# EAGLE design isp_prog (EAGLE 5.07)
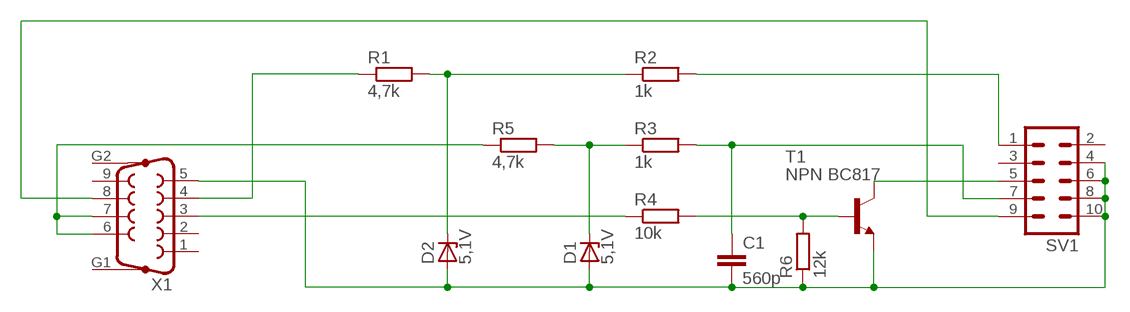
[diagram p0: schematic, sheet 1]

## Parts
C1  560p  C-EUC0805  [C0805]
D1  5,1V  ZENER-DIODESOD80C  [SOD80C]
D2  5,1V  ZENER-DIODESOD80C  [SOD80C]
R1  4,7k  R-EU_R0805  [R0805]
R2  1k  R-EU_R0805  [R0805]
R3  1k  R-EU_R0805  [R0805]
R4  10k  R-EU_R0805  [R0805]
R5  4,7k  R-EU_R0805  [R0805]
R6  12k  R-EU_R0805  [R0805]
SV1  ML10  [ML10]
T1  NPN BC817  BC817-16-NPN-SOT23-BEC  [SOT23-BEC]
X1  F09HP  [F09HP]

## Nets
GND: C1.2 D1.A D2.A R6.1 SV1.4 SV1.6 SV1.8 SV1.10 T1.E X1.5
N$2: R4.2 R6.2 T1.B
N$4: SV1.5 T1.C
N$5: D2.C R1.2 R2.1
N$6: D1.C R3.1 R5.2
N$7: C1.1 R3.2 SV1.7
N$8: R4.1 X1.3
N$9: R5.1 X1.6 X1.7
N$10: R2.2 SV1.1
N$11: SV1.9 X1.8
N$12: R1.1 X1.4
Unconnected: SV1.2 SV1.3 X1.1 X1.2 X1.9 X1.G1 X1.G2

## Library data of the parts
C1 = rcl:C-EU: CAPACITOR, European symbol
D1 D2 = diode:ZENER-DIODE: Z-Diode
R1-R6 = resistor:R-EU_: RESISTOR, European symbol
SV1 = con-harting-ml:ML10: HARTING
T1 = transistor:*-NPN-: NPN Transistror BF959 corrected 2008.03.06
X1 = con-subd:F09HP: SUB-D

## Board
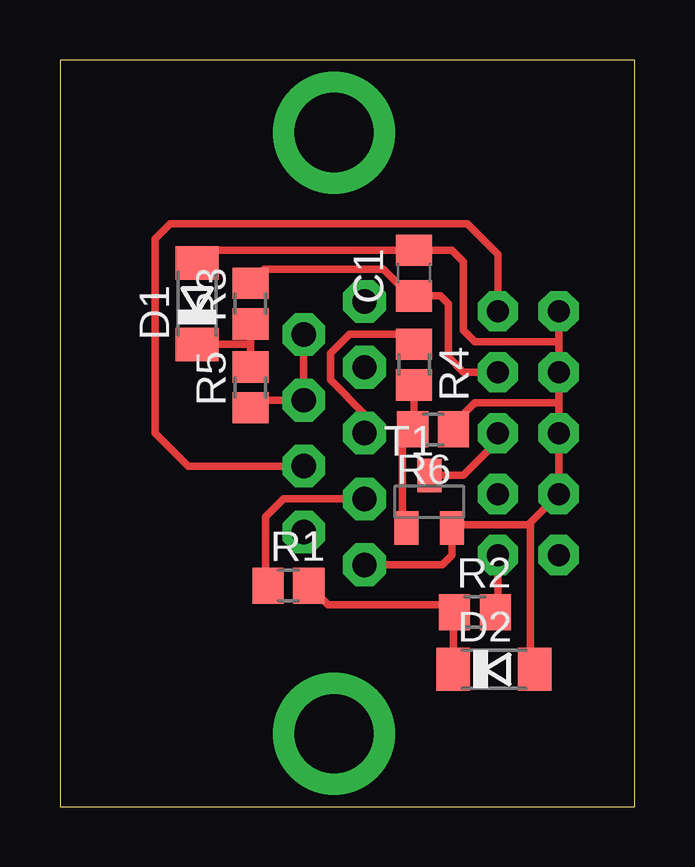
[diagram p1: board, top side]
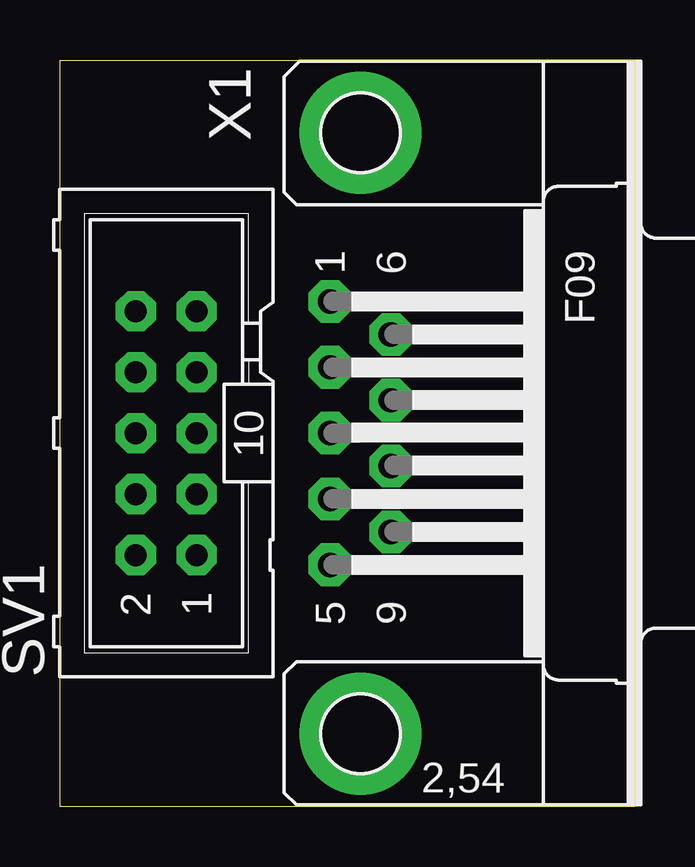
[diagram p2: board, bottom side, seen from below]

Size 23.96 x 31.11 mm. Coordinates in mm from the lower left corner, seen from the top.
Outline: 0,0 23.96,0 23.96,31.11 0,31.11 0,0
Copper layers (1*16): Top 0.035mm / dielectric 1.5mm / Bottom 0.035mm
Design rules "default *": minimum track width 10mil, minimum drill 24mil, track to track 8mil, track to pad 8mil, pad to pad 8mil, via to via 8mil, smd to smd 8mil, copper to edge 40mil, drill to drill 8mil, minimum pad ring 15mil, minimum via ring 8mil, stop-mask expansion 4mil, vias tented up to drill 0mil, thermal gap 10mil

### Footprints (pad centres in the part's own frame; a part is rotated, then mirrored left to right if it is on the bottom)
C0805 = smd 1.3 x 1.5: 1 -0.95,0; 2 0.95,0
SOD80C = smd 1.4 x 1.8: A 1.7,0; C -1.7,0
R0805 = smd 1.3 x 1.5: 1 -0.85,0; 2 0.85,0
ML10 = drill 0.914 octagon: 1 -5.08,-1.27; 2 -5.08,1.27; 3 -2.54,-1.27; 4 -2.54,1.27; 5 0,-1.27; 6 0,1.27; 7 2.54,-1.27; 8 2.54,1.27; 9 5.08,-1.27; 10 5.08,1.27
SOT23-BEC = smd 1 x 1.4: B -0.95,-1.1; C 0,1.1; E 0.95,-1.1
F09HP = drill 1.016 octagon: 1 -5.486,-1.27; 2 -2.743,-1.27; 3 0,-1.27; 4 2.743,-1.27; 5 5.486,-1.27; 6 -4.115,1.27; 7 -1.372,1.27; 8 1.372,1.27; 9 4.115,1.27 | drill 3.302 pad 5.08 round: G1 -12.522,0; G2 12.522,0

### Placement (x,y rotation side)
C1  14.76,22.23 90 top
D1  5.72,20.95 90 top
D2  18.1,5.72 0 top
R1  9.52,9.21 0 top
R2  17.3,8.1 0 top
R3  7.94,20.96 90 top
R4  14.76,18.41 270 top
R5  7.94,17.46 90 top
R6  15.56,15.72 180 top
SV1  19.53,15.56 90 bottom
T1  15.4,12.7 0 top
X1  11.43,15.56 270 bottom

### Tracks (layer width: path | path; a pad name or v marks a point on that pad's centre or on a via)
GND
  Top 0.305: 20.8,16.83 SV1.6 SV1.4 19.61,11.83 | 20.8,16.83 SV1.8 20.8,19.37 | 20.8,19.37 SV1.10 | X1.5 15.95,10.07 16.35,10.48 T1.E 16.52,11.6 16.67,11.75 19.53,11.75 19.61,11.83 | R6.1 16.41,15.93 17.3,16.83 20.8,16.83 | 20.8,19.37 17.3,19.37 16.83,19.84 16.83,22.7 16.35,23.18 C1.2 6.24,23.18 D1.A | 19.61,11.83 19.61,5.91 D2.A
N$2
  Top 0.305: R6.2 14.92,15.72 14.61,15.4 | T1.B 14.29,11.76 14.29,15.3 R6.2 | R4.2 14.76,15.77 R6.2
N$4
  Top 0.305: T1.C 16.82,13.8 17.94,14.92 17.94,15.24 SV1.5
N$5
  Top 0.305: D2.C 16.4,8.04 | 16.4,8.04 R2.1 | 16.4,8.04 16.4,8.05 16.03,8.41 11.17,8.41 R1.2
N$6
  Top 0.305: 7.94,19.21 R3.1 | 7.94,19.21 R5.2 | R3.1 | D1.C 7.89,19.25 7.94,19.21
N$7
  Top 0.305: SV1.7 16.83,18.1 16.19,18.73 16.19,20.95 15.87,21.27 C1.1 14.45,21.59 14.29,21.59 13.49,22.38 8.52,22.38 R3.2
N$8
  Top 0.305: X1.3 12.7,16.35 11.27,17.78 11.27,18.89 12.06,19.68 14.34,19.68 R4.1
N$9
  Top 0.305: X1.6 X1.7 8.25,16.93 R5.1
N$10
  Top 0.305: SV1.1 18.26,8.2 R2.2
N$11
  Top 0.305: X1.8 5.34,14.19 3.97,15.56 3.97,23.65 4.6,24.29 16.99,24.29 18.26,23.02 SV1.9
N$12
  Top 0.305: X1.4 9.32,12.81 8.57,12.06 8.57,9.31 R1.1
